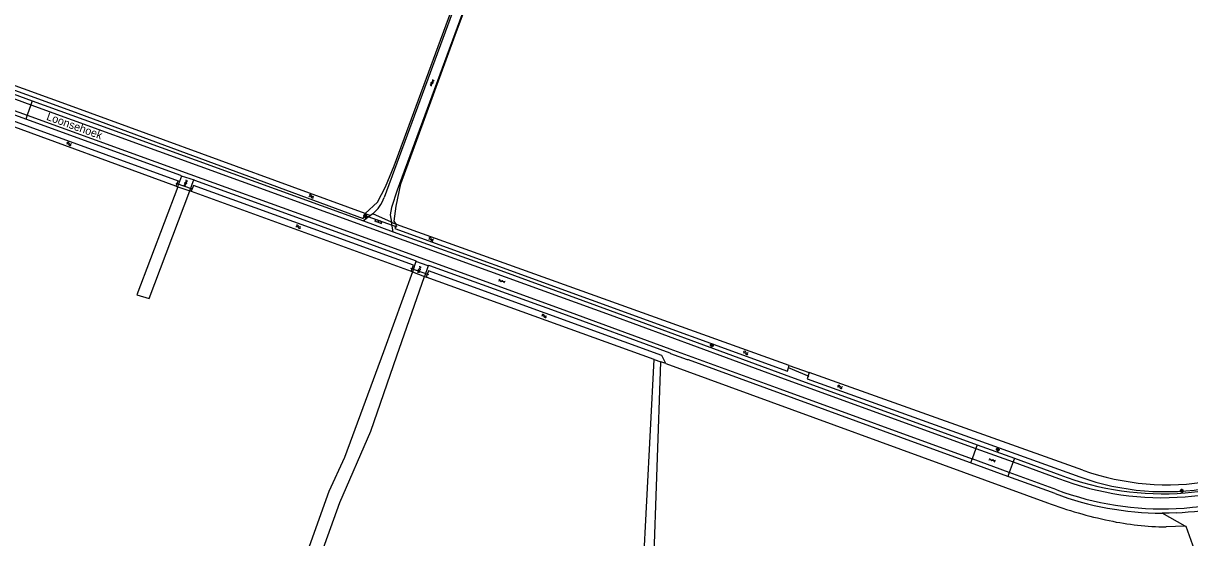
# Model space of a CAD drawing. Extents: x 134297 to 137000, y 403500 to 406000.
# Drawn here: x 135346.8 to 135711.2, y 404321.6 to 404482.3 of the extents above; entities that cross this region are included whole.
import ezdxf

# ---------------------------------------------------------------- set-up
doc = ezdxf.new("R2010")
doc.units = 0
for name, color, linetype in [('gg-afsc-draadraster', 7, 'Continuous'), ('gg-afsc-lijn draadraster', 7, 'Continuous'), ('gg-anno-openbare ruimte label', 7, 'Continuous'), ('gg-knt-bronhoudergrens', 7, 'Continuous'), ('gg-knt-onverhard', 7, 'Continuous'), ('gg-knt-verharding', 7, 'Continuous'), ('gg-knt-verharding nz', 7, 'Continuous'), ('gg-kntw-bovenkant insteek waterloop', 7, 'Continuous'), ('gg-kwrk-duiker nz buis', 7, 'Continuous'), ('gt-grn-groengrens', 7, 'Continuous'), ('gt-grn-vlakafsluiter', 7, 'Continuous'), ('gt-grn-weggrens', 7, 'Continuous'), ('gt-symb-gesloten verharding', 7, 'Continuous'), ('gt-symb-klinker verharding', 7, 'Continuous'), ('gt-symb-lichtmast', 7, 'Continuous'), ('gt-symb-watersymbool', 7, 'Continuous')]:
    doc.layers.add(name, color=color, linetype=linetype)

# ---------------------------------------------------------------- blocks, each defined once
blk = doc.blocks.new('gt0-KL1')
at = {"layer": 'gt-symb-klinker verharding'}
for p, q in [((-1.15, 0.3), (1.15, 0.3)), ((-1, -0.3), (-1, 0.3)), ((-0.5, 0.3), (-0.5, 0.45)), ((0, -0.3), (0, 0.3)), ((0.5, 0.3), (0.5, 0.45)), ((1, -0.3), (1, 0.3)), ((-1.15, -0.3), (1.15, -0.3)), ((-0.5, -0.45), (-0.5, -0.3)), ((0.5, -0.45), (0.5, -0.3))]:
    blk.add_line(p, q, dxfattribs=at)
blk = doc.blocks.new('gt0-GESVH1')
at = {"layer": 'gt-symb-gesloten verharding'}
for p, q in [((-0.99, -0.26), (0.01, 0.24)), ((0.01, -0.26), (-0.99, 0.24)), ((0.01, 0.24), (1.01, -0.26)), ((1.01, 0.24), (0.01, -0.26))]:
    blk.add_line(p, q, dxfattribs=at)
blk = doc.blocks.new('gt0-WA')
at = {"layer": 'gt-symb-watersymbool'}
for centre, start, end in [((-0.32, 0.02), 28.0725, 151.9275), ((0.43, 0.42), 208.0725, 331.9275), ((-0.32, -0.43), 28.0725, 151.9275), ((0.43, -0.03), 208.0725, 331.9275)]:
    blk.add_arc(centre, 0.425, start, end, dxfattribs=at)
blk = doc.blocks.new('gt0-LMAST')
at = {"layer": 'gt-symb-lichtmast'}
for p, q in [((-0.18, 0.17), (-0.45, 0.44)), ((-0.01, 0.25), (-0.01, 0.62)), ((0.17, 0.17), (0.44, 0.44)), ((-0.26, 0), (-0.63, 0)), ((-0.18, -0.18), (-0.45, -0.45)), ((-0.01, -0.25), (-0.01, -0.63)), ((0.44, -0.45), (0.17, -0.18)), ((0.24, 0), (0.62, 0))]:
    blk.add_line(p, q, dxfattribs=at)
blk.add_circle((-0.01, 0), 0.25, dxfattribs=at)

msp = doc.modelspace()

# ---------------------------------------------------------------- linework, layer by layer
at = {"layer": 'gg-afsc-draadraster'}
for points in [[(135453.59, 404422.86), (135457.43, 404426.45), (135459.98, 404431.23), (135462.69, 404437.81), (135498.12, 404533.88), (135502.5, 404545.75), (135509.37, 404564.37), (135516.23, 404583.7)], [(135463.38, 404419.49), (135462.67, 404420.47), (135463.32, 404425.22), (135464.79, 404432.11), (135470.14, 404446.89), (135481.76, 404478.65), (135489.89, 404500.46), (135505.71, 404543.44), (135516.19, 404571.92), (135518.38, 404576.53), (135527.81, 404573.94), (135597.73, 404557.48)]]:
    msp.add_lwpolyline(points, dxfattribs=at)
at = {"layer": 'gg-afsc-lijn draadraster'}
msp.add_lwpolyline([(135463.38, 404419.49), (135462.67, 404420.47), (135463.32, 404425.22), (135464.79, 404432.11), (135470.14, 404446.89), (135481.76, 404478.65), (135489.89, 404500.46), (135505.71, 404543.44), (135516.19, 404571.92), (135518.38, 404576.53), (135527.81, 404573.94), (135597.73, 404557.48)], dxfattribs=at)
at = {"layer": 'gg-knt-bronhoudergrens'}
for p, q in [((135468.38, 404404.68), (135459.38, 404379.63)), ((135463.5, 404378.41), (135472.11, 404403.23))]:
    msp.add_line(p, q, dxfattribs=at)
for points in [[(135395.03, 404431.21), (135382.27, 404397.51), (135386.07, 404396.3), (135398.85, 404429.99)], [(135459.38, 404379.63), (135447.2, 404346.69), (135442.22, 404336.02), (135430.02, 404301.66), (135434.03, 404300.15), (135445.65, 404332.63), (135455.4, 404354.91), (135463.5, 404378.41)]]:
    msp.add_lwpolyline(points, dxfattribs=at)
at = {"layer": 'gg-knt-onverhard'}
for p, q in [((135709.84, 404325.22), (135702.6, 404329.26)), ((135710.12, 404325.06), (135709.84, 404325.22)), ((135722.25, 404291.15), (135710.12, 404325.06))]:
    msp.add_line(p, q, dxfattribs=at)
at = {"layer": 'gg-knt-verharding'}
for p, q in [((135515.82, 404580.75), (135459.55, 404427.83)), ((135338.68, 404462.01), (135349.51, 404458.09)), ((135347.55, 404452.33), (135336.6, 404456.3)), ((135349.1, 404456.88), (135347.98, 404453.6)), ((135349.51, 404458.09), (135349.1, 404456.88)), ((135347.98, 404453.6), (135347.55, 404452.33)), ((135396.2, 404434.57), (135394.95, 404431.24)), ((135400.27, 404433.25), (135396.2, 404434.57)), ((135455.27, 404422.28), (135453.09, 404420.54)), ((135453.09, 404420.54), (135462.37, 404417.17)), ((135461.86, 404420.15), (135455.97, 404422.82)), ((135462.37, 404417.17), (135461.86, 404420.15)), ((135469.47, 404407.93), (135468.35, 404404.7)), ((135473.26, 404406.49), (135469.47, 404407.93)), ((135473.26, 404406.49), (135472.11, 404403.23)), ((135644.85, 404350.65), (135644.43, 404349.48)), ((135644.85, 404350.65), (135656.47, 404346.41)), ((135644.43, 404349.48), (135643.23, 404346.19)), ((135643.23, 404346.19), (135642.78, 404344.96)), ((135654.39, 404340.74), (135642.78, 404344.96)), ((135656.04, 404345.25), (135654.83, 404341.96)), ((135656.47, 404346.41), (135656.04, 404345.25)), ((135656.47, 404346.41), (135670.63, 404341.25)), ((135654.83, 404341.96), (135654.39, 404340.74)), ((135669.17, 404335.37), (135654.39, 404340.74))]:
    msp.add_line(p, q, dxfattribs=at)
for points in [[(135517.37, 404575.96), (135463.59, 404430.14), (135461.79, 404424.79), (135461.47, 404422.44), (135461.86, 404420.15)], [(135349.51, 404458.09), (135378.12, 404447.77), (135412.29, 404435.34), (135453.09, 404420.54)], [(135396.2, 404434.57), (135396.04, 404434.8), (135347.55, 404452.33)], [(135398.79, 404430.01), (135399.95, 404433.21), (135400.27, 404433.25)], [(135400.27, 404433.25), (135434.43, 404420.86), (135469.28, 404408.24), (135469.4, 404408.1), (135469.47, 404407.93)], [(135455.97, 404422.82), (135455.96, 404422.82), (135455.27, 404422.28)], [(135462.37, 404417.17), (135495.96, 404405.02), (135530.16, 404392.58), (135584.58, 404372.61), (135644.85, 404350.65)], [(135642.78, 404344.96), (135625.24, 404351.33), (135583.34, 404366.6), (135554.67, 404377.12), (135554.32, 404377.17), (135549.1, 404379.07), (135548.92, 404379.24), (135514.24, 404391.9), (135473.83, 404406.57)], [(135707.02, 404329.35), (135704.81, 404329.27), (135702.6, 404329.26)]]:
    msp.add_lwpolyline(points, dxfattribs=at)
for centre, radius, start, end in [((135448.8, 404431.72), 11.43, 308.8316, 340.1103), ((135473.6, 404406.09), 0.53, 64.7923, 129.7323), ((135702.17, 404432.43), 97.15, 274.5328, 293.2646), ((135702.77, 404425.18), 89.87, 249.0477, 274.5191), ((135702.86, 404425.09), 95.83, 249.4157, 269.8438), ((135700.86, 404440.33), 111.16, 273.1775, 281.0098)]:
    msp.add_arc(centre, radius, start, end, dxfattribs=at)
at = {"layer": 'gg-knt-verharding nz'}
for p, q in [((135338.24, 404460.8), (135349.1, 404456.88)), ((135337.05, 404457.55), (135347.98, 404453.6)), ((135644.43, 404349.48), (135656.04, 404345.25)), ((135654.83, 404341.96), (135643.23, 404346.19)), ((135656.04, 404345.25), (135670.3, 404340.07)), ((135669.69, 404336.55), (135654.83, 404341.96))]:
    msp.add_line(p, q, dxfattribs=at)
for points in [[(135349.1, 404456.88), (135454.8, 404418.55), (135530.15, 404391.17), (135584.49, 404371.27), (135644.43, 404349.48)], [(135347.98, 404453.6), (135398.86, 404435.17), (135435.15, 404422.01), (135514.51, 404393.19), (135548.85, 404380.64), (135583.2, 404368.06), (135643.23, 404346.19)]]:
    msp.add_lwpolyline(points, dxfattribs=at)
for centre, radius, start, end in [((135702.71, 404424.69), 90.61, 249.0399, 274.5121), ((135701.35, 404438.77), 108.23, 272.9853, 294.6764), ((135702.21, 404432.79), 98.73, 274.4304, 293.1408), ((135702.76, 404425.21), 94.63, 249.547, 272.558)]:
    msp.add_arc(centre, radius, start, end, dxfattribs=at)
at = {"layer": 'gg-kntw-bovenkant insteek waterloop'}
for p, q in [((135394.41, 404431.41), (135325.5, 404456.69)), ((135399.28, 404429.86), (135467.94, 404404.86)), ((135586.09, 404375.44), (135463.38, 404419.49)), ((135543.93, 404377.31), (135472.72, 404402.99)), ((135547.54, 404376.01), (135545.98, 404376.58)), ((135677.88, 404342.72), (135592.32, 404373.23))]:
    msp.add_line(p, q, dxfattribs=at)
for points in [[(135293.04, 404481.36), (135292.55, 404480.09), (135361.9, 404454.91), (135452.98, 404421.36), (135453.59, 404422.86)], [(135453.59, 404422.86), (135362.39, 404456.18), (135293.04, 404481.36)], [(135325.5, 404456.69), (135326.15, 404458.2), (135395.18, 404433.08), (135394.41, 404431.41)], [(135467.94, 404404.86), (135468.71, 404406.69), (135399.95, 404431.62), (135399.28, 404429.86)], [(135463.38, 404419.49), (135462.85, 404418.2), (135585.6, 404373.64), (135586.09, 404375.44)], [(135547.54, 404376.01), (135546.33, 404378.52), (135473.45, 404404.93), (135472.72, 404402.99)], [(135280.16, 404283.76), (135322.3, 404271.13), (135470.13, 404227.94), (135536.41, 404209.42), (135536.94, 404210.74), (135540.51, 404311.02), (135543.93, 404377.31)], [(135538.9, 404204.96), (135539.77, 404209.82), (135542.57, 404277.8), (135545.98, 404376.58)], [(135592.32, 404373.23), (135591.73, 404371.26), (135676.94, 404340.57)]]:
    msp.add_lwpolyline(points, dxfattribs=at)
for centre, radius, start, end in [((135703.54, 404415.03), 79.07, 250.3395, 280.3706), ((135704.18, 404415.49), 77.37, 250.134, 280.1604)]:
    msp.add_arc(centre, radius, start, end, dxfattribs=at)
at = {"layer": 'gg-kwrk-duiker nz buis'}
for p, q in [((135399.64, 404430.52), (135394.55, 404432.3)), ((135453, 404422.48), (135463.53, 404418.69)), ((135473.52, 404403.73), (135467.93, 404405.68)), ((135585.78, 404374.73), (135592.26, 404372.03))]:
    msp.add_line(p, q, dxfattribs=at)
at = {"layer": 'gt-grn-groengrens'}
for p, q in [((135394.41, 404431.41), (135394.95, 404431.24)), ((135394.95, 404431.24), (135395.03, 404431.21)), ((135398.85, 404429.99), (135399.28, 404429.86)), ((135453.59, 404422.86), (135455.27, 404422.28)), ((135461.86, 404420.15), (135463.38, 404419.49)), ((135467.94, 404404.86), (135468.35, 404404.7)), ((135468.35, 404404.7), (135468.38, 404404.68)), ((135472.11, 404403.23), (135472.72, 404402.99)), ((135547.54, 404376.01), (135666.82, 404332.5)), ((135586.09, 404375.44), (135592.32, 404373.23))]:
    msp.add_line(p, q, dxfattribs=at)
msp.add_lwpolyline([(135709.84, 404325.22), (135706.86, 404325.04), (135703.88, 404324.97)], dxfattribs=at)
for centre, radius, start, end in [((135713.6, 404458.34), 134.26, 249.6053, 258.1939), ((135704.97, 404416.38), 91.42, 258.1066, 269.3144)]:
    msp.add_arc(centre, radius, start, end, dxfattribs=at)
at = {"layer": 'gt-grn-vlakafsluiter'}
msp.add_line((135543.93, 404377.31), (135545.98, 404376.58), dxfattribs=at)
at = {"layer": 'gt-grn-weggrens'}
for p, q in [((135395.03, 404431.21), (135398.79, 404430.01)), ((135398.79, 404430.01), (135398.85, 404429.99)), ((135468.38, 404404.68), (135472.11, 404403.23))]:
    msp.add_line(p, q, dxfattribs=at)

# ---------------------------------------------------------------- block references
at = {"layer": 'gt-symb-gesloten verharding'}
for p, rotation in [((135474.5, 404463.73), 67.97515406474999), ((135397.53, 404432.37), -108.48932632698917), ((135470.55, 404405.36), -108.12681251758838), ((135496.28, 404401.77), -19.939047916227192), ((135649.51, 404345.81), -19.939047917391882)]:
    msp.add_blockref('gt0-GESVH1', p, dxfattribs=dict(at, rotation=rotation))
at = {"layer": 'gt-symb-klinker verharding', "rotation": -20.663302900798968}
msp.add_blockref('gt0-KL1', (135457.74, 404420.45), dxfattribs=at)
at = {"layer": 'gt-symb-lichtmast'}
for p in [(135453.69, 404421.98), (135561.98, 404381.75), (135651.32, 404349.17), (135708.78, 404336.24)]:
    msp.add_blockref('gt0-LMAST', p, dxfattribs=at)
at = {"layer": 'gt-symb-watersymbool'}
for p, rotation in [((135361, 404444.62), -8.97262661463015), ((135436.75, 404428.25), -8.9726266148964), ((135432.69, 404418.76), -8.9726266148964), ((135474.14, 404414.85), -8.9726266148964), ((135509.47, 404390.87), -8.97262661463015), ((135572.45, 404379.34), -8.9726266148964), ((135601.88, 404368.7), -8.9726266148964)]:
    msp.add_blockref('gt0-WA', p, dxfattribs=dict(at, rotation=rotation))

# ---------------------------------------------------------------- texts
at = {"layer": 'gg-anno-openbare ruimte label'}
msp.add_text('Loonsehoek', height=2.5, rotation=340.1, dxfattribs=at).set_placement((135353.82, 404452.21))

doc.saveas('drawing.dxf')
